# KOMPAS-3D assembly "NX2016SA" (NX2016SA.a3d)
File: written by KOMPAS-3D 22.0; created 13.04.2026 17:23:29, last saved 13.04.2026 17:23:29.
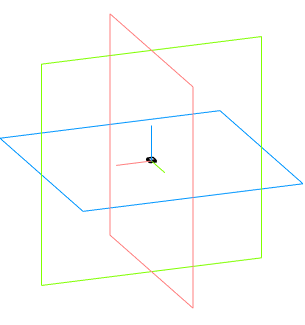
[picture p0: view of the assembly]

Document properties: Автор: Andrey; Полное имя файла: C:\Users\User1\Documents\NX2016SA.a3d

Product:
- Component [assembly]: NX2016SA-40M-STD-CZS-3  | qty 1  | source file: NX2016SA-40M-STD-CZS-3.a3d
- Part/product: NX2016SA
    Комментарий: NX2016SA

Referenced files in C:\Users\User1\Documents\: NX2016SA-40M-STD-CZS-3.a3d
